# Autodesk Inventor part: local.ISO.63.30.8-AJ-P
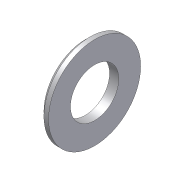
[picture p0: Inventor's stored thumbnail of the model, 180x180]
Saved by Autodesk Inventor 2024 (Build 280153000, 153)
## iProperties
Company: ATC
_DisabledCommands: 0
Created: 2023-03
Part Number: local.ISO.63.30.8-AJ-P
Material: Standard
Description: Podkładka
Vendor: Autodesk Inc.
Document SubType Name: Modeling
Standard: ISO 7090
Designer: Andrzej Jaskulski
Size Designation: 8 - 140 HV
Density: 1 g/cm^3
Appearance: Domyślna
Checked By: A.J.
Engr Approved By: Andrzej Jaskulski
Mfg Approved By: Andrzej Jaskulski
Authority: A.J.
Classification: un/spsc 31161807
Author: Andrzej Jaskulski
Revision Number: 1/24
Title: A.J.: Kurs R2024-MEP
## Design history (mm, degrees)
sketch "Szkic"
  geometry: C1 r 8 at (0, 0); C2 r 4.2 at (0, 0); 1 further point
  constraints: 2 centre point, 2 coincident
  dimensions: "d0" = 8.4 diameter of C2 (= SD1); "d1" = 16 diameter of C1 (= SD2)
extrude "Bryła" new body sketch "Szkic" distance "d2" = 1.6 (= SD); taper "d3" = 0 deg
node "Bryła1"
node "Korpusy bryłowe"
node "Korpusy powierzchniowe"
chamfer "Faza" distance "d4" = 0.8 (= PHH); stored, may be unused: angle "d5" = 45 deg, second distance "d8" = 0.8 (= PHH)
other parameters: "SD1" = 8.4 [user parameter; used in 1 equation term], "SD2" = 16 [user parameter; used in 1 equation term], "SD" = 1.6 [user parameter; used in 1 equation term], "PHH" = 0.8 [user parameter; used in 2 equation terms], "FAWI" = 45 deg [user parameter], "d6" = 0, "d7" = 0, "NND" = 8 [user parameter]
